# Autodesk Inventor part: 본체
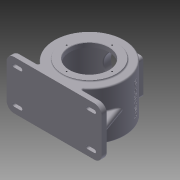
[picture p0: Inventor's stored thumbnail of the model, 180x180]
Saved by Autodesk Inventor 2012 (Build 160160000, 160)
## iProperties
Created: 2015-06
Part Number: 본체
Material: 알루미늄-6061
Document SubType Name: Modeling
Designer: user
Density: 2.71 g/cm^3
Mass: 3275.61 g
Surface Area: 2298.94 cm^2
Volume: 1208.71 cm^3
Author: user
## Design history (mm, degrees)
sketch "스케치1"
  geometry: L1 (-115, 59)-(115, 59); L2 (115, 59)-(115, -59); L3 (115, -59)-(-115, -59); L4 (-115, -59)-(-115, 59); 3 further points
  constraints: 8 end point, 2 midpoint, 2 parallel, 1 horizontal, 1 horizontal alignment, 1 perpendicular, 1 vertical alignment
  dimensions: "d0" = 230 distance of L1.start L1.end; "d1" = 118 distance of L1.end L2.end
extrude "돌출1" new body sketch "스케치1" distance "d2" = 14; taper "d3" = 0 deg
node "작업 평면1"
sketch "스케치2"
  geometry: C1 r 65 at (115, 85); 1 further point
  constraints: 1 centre point, 1 vertical alignment
  dimensions: "d5" = 130 diameter of C1; "d6" = 85 distance of point (115, 0) C1.centre
extrude "돌출2" join sketch "스케치2" distance "d7" = 13; taper "d8" = 0 deg
sketch "스케치3"
  geometry: C1 r 65 at (0, 0) reference; C2 r 85 at (0, 0); 1 further point
  constraints: 1 centre point, 1 coincident
  dimensions: "d9" = 170 diameter of C2
extrude "돌출3" join sketch "스케치3" distance "d10" = 118; taper "d11" = 0 deg
sketch "스케치4"
  geometry: C1 r 65 at (115, 85); A1 r 85 centre (115, 85) between (161.733, 14) and (68.267, 14) reference; 1 further point
  constraints: 1 centre point, 1 coincident
  dimensions: "d12" = 130 diameter of C1
extrude "돌출4" join sketch "스케치4" distance "d13" = 3; taper "d14" = 0 deg
sketch "스케치5"
  geometry: C1 r 65 at (0, 0) reference; C2 r 47.5 at (0, 0); 1 further point
  constraints: 1 centre point, 1 coincident
  dimensions: "d15" = 95 diameter of C2
extrude "돌출5" cut sketch "스케치5" distance "d16" = 11; taper "d17" = 0 deg
sketch "스케치7"
  geometry: L1 (132.5, 51)-(37.5, 51) reference; L2 (85, 51)-(85, -72); L3 (150, -72)-(20, -72) reference; L4 (14, 59)-(14, -59) reference; L5 (85, 51)-(162, 51); L6 (162, 51)-(162, -51); L7 (162, -51)-(116, -51); L8 (116, -51)-(114.368, -47.5); L9 (114.368, -47.5)-(85, -47.5); 1 further point
  constraints: 12 end point, 3 perpendicular, 2 midpoint, 2 point on line
  dimensions: "d19" = 154 diameter of L5.end L2; "d20" = 102 distance of L5.end L6.end; "d21" = 62 diameter of L7.end L2; "d22" = 3.5 vertical distance of L7.end L8.end; "d23" = 115 deg angle of L7 L8
revolve "회전1" sketch "스케치7" stored, may be unused: angle "d24" = 90 deg
sketch "스케치8"
  geometry: C1 r 29.368 at (0, 0) reference; C2 r 23.5 at (0, 0); 1 further point
  constraints: 1 centre point, 1 coincident
  dimensions: "d25" = 47 diameter of C2
extrude "돌출6" cut sketch "스케치8" distance "d26" = 14; taper "d27" = 0 deg
sketch "스케치9"
  geometry: C1 r 23.5 at (0, 0) reference; C2 r 15 at (0, 0); 1 further point
  constraints: 1 centre point, 1 coincident
  dimensions: "d28" = 30 diameter of C2
extrude "돌출7" cut sketch "스케치9" distance "d29" = 3; taper "d30" = 0 deg
sketch "스케치11"
  geometry: L1 (-115, 59)-(115, 59) reference; L2 (0, 59)-(0, -59); L3 (-115, -59)-(-115, 59) reference; L4 (-115, 0)-(115, 0); L5 (115, 59)-(115, -59) reference; L6 (-97, 50)-(-81, 50); L7 (-97, 32)-(-81, 32); L8 (-97, -50)-(-81, -50); L9 (-97, -32)-(-81, -32); A1 r 9 centre (-97, 41) between (-97, 50) and (-97, 32); A2 r 9 centre (-81, 41) between (-81, 32) and (-81, 50); A3 r 9 centre (-97, -41) between (-97, -32) and (-97, -50); A4 r 9 centre (-81, -41) between (-81, -50) and (-81, -32); 3 further points
  constraints: 12 end point, 8 point on circle, 6 symmetric about line, 5 midpoint, 4 centre point, 4 coincident, 3 perpendicular, 3 tangent, 1 parallel, 2 other
  dimensions: "d40" = 18 diameter of A1; "d41" = 18 diameter of A2; "d42" = 16 distance of A2.centre A1.centre; "d43" = 194 diameter of A1.centre L2; "d44" = 82 diameter of A1.centre L4
extrude "돌출9" join sketch "스케치11" distance "d45" = 3; taper "d46" = 0 deg
sketch "스케치13"
  geometry: L1 (-97, 45)-(-81, 45); L2 (-97, 37)-(-81, 37); A1 r 9 centre (-97, 41) between (-97, 50) and (-97, 32) reference; A2 r 9 centre (-81, 41) between (-81, 32) and (-81, 50) reference; A3 r 4 centre (-97, 41) between (-97, 45) and (-97, 37); A4 r 4 centre (-81, 41) between (-81, 37) and (-81, 45); 1 further point
  constraints: 4 end point, 4 point on circle, 3 tangent, 2 centre point, 2 coincident, 1 parallel
  dimensions: "d47" = 8 diameter of A3; "d48" = 8 diameter of A4
extrude "돌출10" cut sketch "스케치13" stored distance "d49" = 3; taper "d50" = 0 deg
sketch "스케치14"
  geometry: L1 (-115, 14)-(-46.733, 14) reference; L2 (-109, 14)-(-84.87, 80.297); L3 (-109, 14)-(-46.733, 14); A1 r 85 centre (0, 85) between (46.733, 14) and (-46.733, 14) reference; 1 further point
  constraints: 4 end point, 1 collinear, 1 point on circle, 1 point on line
  dimensions: "d52" = 110 deg angle of L1 L2; "d53" = 6 distance of L2.start L1.start
extrude "돌출11" join sketch "스케치14" stored distance "d54" = 15; taper "d55" = 0 deg
node "작업 평면2"
sketch "스케치15"
  geometry: L1 (-42.5, 42.5)-(42.5, 42.5); L2 (42.5, 42.5)-(42.5, -42.5); L3 (42.5, -42.5)-(-42.5, -42.5); L4 (-42.5, -42.5)-(-42.5, 42.5); 3 further points
  constraints: 8 end point, 2 midpoint, 2 parallel, 2 perpendicular, 1 horizontal, 1 horizontal alignment, 1 vertical alignment
  dimensions: "d57" = 85 distance of L1.start L1.end
extrude "돌출12" join sketch "스케치15" stored distance "d58" = 15; taper "d59" = 0 deg
sketch "스케치16"
  geometry: C1 r 35 at (0, 0); 1 further point
  constraints: 1 centre point, 1 coincident
  dimensions: "d60" = 70 diameter of C1
extrude "돌출13" cut sketch "스케치16" stored distance "d61" = 15; taper "d62" = 0 deg
sketch "스케치18"
  geometry: C1 r 47.5 at (0, 0) reference; 2 further points
  constraints: 1 vertical alignment
  dimensions: "d64" = 55 distance of C1.centre point (0, 55)
hole "구멍1" sketch "스케치18" at (0, 55) diameter "d65" = 3.242; stored, may be unused: countersink angle "d69" = 90 deg, drill point angle "d71" = 0 deg; dims "d66" = 11, "d67" = 4, "d68" = 2, "d70" = 8
sketch "스케치19"
  geometry: L1 (42.5, -42.5)-(-42.5, -42.5) reference; L2 (42.5, 42.5)-(42.5, -42.5) reference; L3 (-42.5, 42.5)-(42.5, 42.5) reference; L4 (-42.5, -42.5)-(-42.5, 42.5) reference; L5 (-42.5, 0)-(42.5, 0); L6 (0, 42.5)-(0, -42.5); 1 further point
  constraints: 4 end point, 4 midpoint
  dimensions: "d75" = 71 diameter of point (-35.5, 35.5) L6; "d76" = 71 diameter of point (-35.5, 35.5) L5
hole "구멍2" sketch "스케치19" at (-35.5, 35.5) diameter "d77" = 3.242; stored, may be unused: countersink angle "d81" = 90 deg, drill point angle "d83" = 118 deg; dims "d78" = 10, "d79" = 4, "d80" = 2, "d82" = 13
fillet "모깎기2" dims "d85" = 7.5
fillet "모깎기3" dims "d86" = 7
fillet "모깎기4" dims "d87" = 3
fillet "모깎기5" dims "d88" = 3
fillet "모깎기7" dims "d90" = 18
fillet "모깎기9" dims "d92" = 3
fillet "모깎기10" dims "d93" = 3
fillet "모깎기11" dims "d94" = 3
chamfer "모따기1" distance "d95" = 1; stored, may be unused: second distance "d96" = 2, angle "d97" = 45 deg
chamfer "모따기2" distance "d98" = 1; stored, may be unused: second distance "d99" = 2, angle "d100" = 45 deg
chamfer "모따기3" distance "d101" = 1; stored, may be unused: second distance "d102" = 2, angle "d103" = 45 deg
node "작업 평면4"
  node "작업 평면3"
sketch "스케치20"
  geometry: 2 further points
  constraints: 1 horizontal alignment, 1 other
feature "엠보싱1" sketch "스케치20" dims "d104" = 0.5, "d105" = 0
fillet "모깎기13" dims "d107" = 3
fillet "모깎기14" dims "d108" = 3
fillet "모깎기15" dims "d109" = 0.3
fillet "모깎기16" dims "d110" = 3
fillet "모깎기17" dims "d111" = 3
node "솔리드1"
mirror "대칭1"
mirror "대칭2"
mirror "대칭3"
mirror "대칭4"
pattern_circular "원형 패턴1" dims angle "d73" = 360 deg
mirror "대칭5"
mirror "대칭6"
other parameters: "d4" = 13, "d56" = -173
